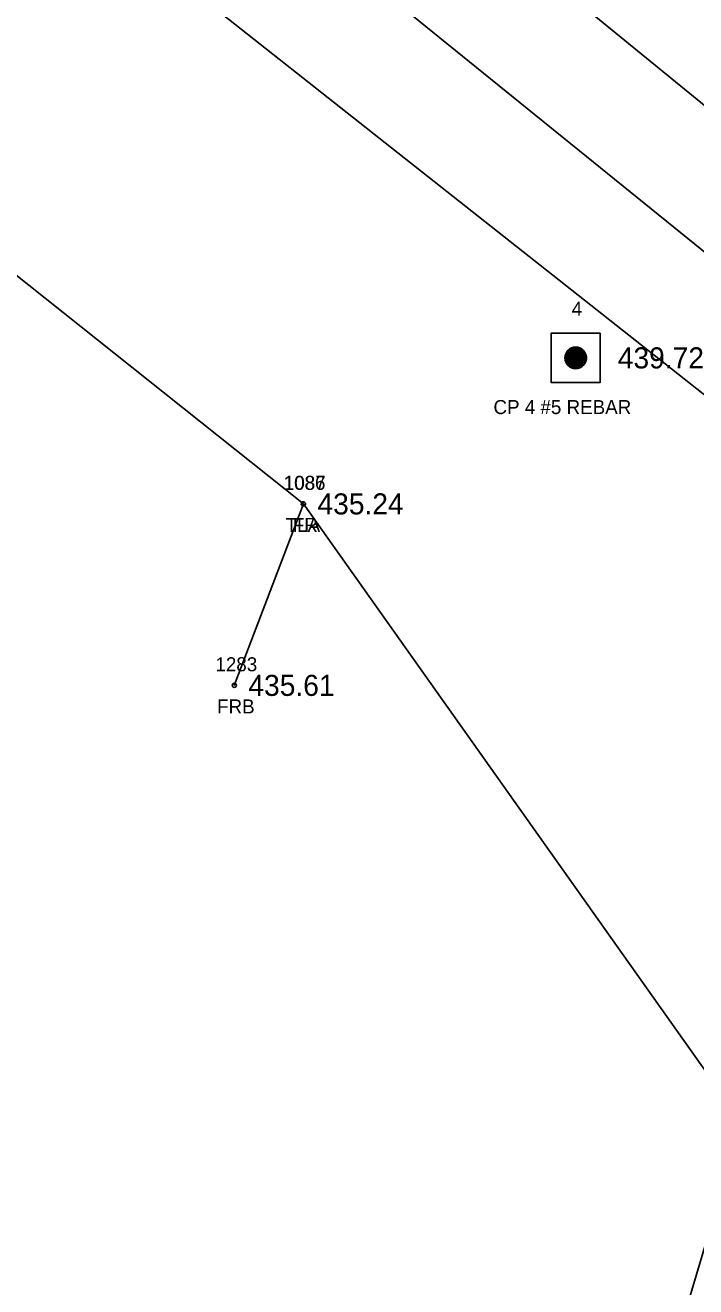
# Model space of a CAD drawing. Extents: x 1611865 to 1617004, y 775289 to 778546.
# Drawn here: x 1614381.3 to 1614429, y 777648.2 to 777738.1 of the extents above; entities that cross this region are included whole.
import ezdxf

# ---------------------------------------------------------------- set-up
doc = ezdxf.new("R2010")
doc.units = 0
for name, color, linetype in [('Default', 7, 'Continuous'), ('RD_EX_Fence_Other', 7, 'Continuous'), ('RD_EX_Fence_Other_txCode', 7, 'Continuous'), ('RD_EX_H2O', 7, 'Continuous'), ('RD_EX_Road', 7, 'Continuous'), ('RD_EX_TX_Fence_Other_ELEV', 7, 'Continuous'), ('RD_EX_TX_VEG_ELEV', 7, 'Continuous'), ('RD_EX_VEG', 7, 'Continuous'), ('RD_EX_VEG_txCode', 7, 'Continuous'), ('RD_HC_Cl', 7, 'Continuous'), ('RD_HC_Data', 7, 'Continuous'), ('RD_HC_Survey', 7, 'Continuous'), ('RD_HC_Survey_ELEV', 7, 'Continuous'), ('RD_HC_Survey_txCode', 7, 'Continuous'), ('RD_SMD_Locator', 7, 'Continuous')]:
    doc.layers.add(name, color=color, linetype=linetype)

msp = doc.modelspace()

# ---------------------------------------------------------------- linework, layer by layer
at = {"layer": 'Default'}
msp.add_line((1614235.771, 777878.843), (1615250.563, 777057.494), dxfattribs=at)
at = {"layer": 'RD_EX_Fence_Other'}
msp.add_lwpolyline([(1613852.079, 778066.008), (1613898.032, 778046.625), (1613942.243, 778026.725), (1613986.541, 778004.123), (1614028.517, 777979.951), (1614066.848, 777959.391), (1614112.817, 777929.404), (1614150.644, 777902.776), (1614189.706, 777873.346), (1614229.911, 777841.274), (1614268.423, 777810.693), (1614347.333, 777746.805), (1614401.116, 777703.978), (1614396.197, 777691.061)], dxfattribs=at)
at = {"layer": 'RD_EX_H2O'}
msp.add_lwpolyline([(1614634.128, 778230.422), (1614629.458, 778175.603), (1614612.201, 778126.551), (1614606.674, 778108.168), (1614610.575, 778089.24), (1614615.98, 778055.093), (1614603.68, 778033.92), (1614586.842, 777977.495), (1614567.105, 777927.459), (1614559.226, 777908.739), (1614527.556, 777868.787), (1614521.381, 777849.921), (1614507.997, 777820.034), (1614493.755, 777779.644), (1614479.272, 777749.866), (1614469.018, 777727.632), (1614464.372, 777721.672), (1614444.521, 777689.773), (1614435.763, 777671.493), (1614423.173, 777629.214)], dxfattribs=at)
at = {"layer": 'RD_EX_Road'}
for points in [[(1613868.873, 778104.152), (1613915.019, 778083.817), (1613960.162, 778062.2), (1614004.584, 778040.278), (1614048.838, 778015.985), (1614091.382, 777990.075), (1614134.355, 777962.6), (1614174.732, 777933.477), (1614192.07, 777920.583), (1614215.929, 777904.228), (1614254.595, 777873.045), (1614293.817, 777842.42), (1614371.745, 777779.588), (1614449.335, 777716.298), (1614443.983, 777709.717), (1614439.382, 777704.087)], [(1613862.136, 778087.922), (1613908.119, 778068.215), (1613952.955, 778047.38), (1613997.003, 778025.093), (1614041.162, 778001.628), (1614124.347, 777949.055), (1614164.513, 777920.905), (1614187.107, 777904.29), (1614205.267, 777889.822), (1614244.492, 777859.521), (1614283.421, 777829.445), (1614361.059, 777765.885), (1614439.382, 777704.087)]]:
    msp.add_lwpolyline(points, dxfattribs=at)
at = {"layer": 'RD_EX_VEG'}
msp.add_line((1614401.116, 777703.978), (1614430.331, 777662.765), dxfattribs=at)
at = {"layer": 'RD_HC_Cl'}
msp.add_line((1614235.771, 777878.843), (1615250.563, 777057.494), dxfattribs=at)
at = {"layer": 'RD_HC_Survey'}
for p, q in [((1614420.341, 777713.618), (1614420.341, 777715.125)), ((1614420.366, 777713.613), (1614420.366, 777715.13)), ((1614420.39, 777713.609), (1614420.39, 777715.134)), ((1614420.415, 777713.606), (1614420.415, 777715.137)), ((1614420.44, 777713.604), (1614420.44, 777715.139)), ((1614420.465, 777713.603), (1614420.465, 777715.14)), ((1614420.489, 777713.602), (1614420.489, 777715.141)), ((1614420.514, 777713.602), (1614420.514, 777715.141)), ((1614420.539, 777713.603), (1614420.539, 777715.14)), ((1614420.564, 777713.605), (1614420.564, 777715.138)), ((1614420.588, 777713.608), (1614420.588, 777715.135)), ((1614420.613, 777713.611), (1614420.613, 777715.132)), ((1614420.638, 777713.615), (1614420.638, 777715.128)), ((1614419.747, 777714.192), (1614419.747, 777714.55)), ((1614419.772, 777714.11), (1614419.772, 777714.633)), ((1614419.796, 777714.049), (1614419.796, 777714.693)), ((1614419.821, 777714), (1614419.821, 777714.742)), ((1614419.846, 777713.959), (1614419.846, 777714.784)), ((1614419.871, 777713.922), (1614419.871, 777714.821)), ((1614419.895, 777713.889), (1614419.895, 777714.853)), ((1614419.92, 777713.86), (1614419.92, 777714.883)), ((1614419.945, 777713.834), (1614419.945, 777714.909)), ((1614419.97, 777713.809), (1614419.97, 777714.933)), ((1614419.994, 777713.787), (1614419.994, 777714.956)), ((1614420.019, 777713.767), (1614420.019, 777714.976)), ((1614420.044, 777713.748), (1614420.044, 777714.995)), ((1614420.069, 777713.731), (1614420.069, 777715.012)), ((1614420.093, 777713.715), (1614420.093, 777715.028)), ((1614420.118, 777713.701), (1614420.118, 777715.042)), ((1614420.143, 777713.687), (1614420.143, 777715.055)), ((1614420.168, 777713.675), (1614420.168, 777715.068)), ((1614420.192, 777713.664), (1614420.192, 777715.079)), ((1614420.217, 777713.654), (1614420.217, 777715.089)), ((1614420.242, 777713.645), (1614420.242, 777715.098)), ((1614420.267, 777713.637), (1614420.267, 777715.106)), ((1614420.291, 777713.629), (1614420.291, 777715.113)), ((1614420.316, 777713.623), (1614420.316, 777715.12)), ((1614420.663, 777713.62), (1614420.663, 777715.122)), ((1614420.687, 777713.626), (1614420.687, 777715.117)), ((1614420.712, 777713.633), (1614420.712, 777715.11)), ((1614420.737, 777713.641), (1614420.737, 777715.102)), ((1614420.762, 777713.649), (1614420.762, 777715.093)), ((1614420.786, 777713.659), (1614420.786, 777715.084)), ((1614420.811, 777713.67), (1614420.811, 777715.073)), ((1614420.836, 777713.681), (1614420.836, 777715.061)), ((1614420.861, 777713.694), (1614420.861, 777715.049)), ((1614420.885, 777713.708), (1614420.885, 777715.035)), ((1614420.91, 777713.723), (1614420.91, 777715.019)), ((1614420.935, 777713.74), (1614420.935, 777715.003)), ((1614420.96, 777713.758), (1614420.96, 777714.985)), ((1614420.984, 777713.777), (1614420.984, 777714.965)), ((1614421.009, 777713.799), (1614421.009, 777714.944)), ((1614421.034, 777713.822), (1614421.034, 777714.921)), ((1614421.059, 777713.847), (1614421.059, 777714.896)), ((1614421.083, 777713.875), (1614421.083, 777714.868)), ((1614421.108, 777713.906), (1614421.108, 777714.837)), ((1614421.133, 777713.941), (1614421.133, 777714.802)), ((1614421.158, 777713.98), (1614421.158, 777714.763)), ((1614421.182, 777714.025), (1614421.182, 777714.718)), ((1614421.207, 777714.079), (1614421.207, 777714.664)), ((1614421.232, 777714.149), (1614421.232, 777714.594)), ((1614421.257, 777714.26), (1614421.257, 777714.483))]:
    msp.add_line(p, q, dxfattribs=at)
msp.add_lwpolyline([(1614422.245, 777716.121), (1614418.745, 777716.121), (1614418.745, 777712.621), (1614422.245, 777712.621)], close=True, dxfattribs=at)
msp.add_circle((1614420.495, 777714.371), 0.769, dxfattribs=at)
at = {"layer": 'RD_SMD_Locator'}
for centre in [(1614420.495, 777714.371), (1614401.116, 777703.978), (1614401.116, 777703.978), (1614396.197, 777691.061)]:
    msp.add_circle(centre, 0.15, dxfattribs=at)

# ---------------------------------------------------------------- texts
at = {"layer": 'RD_EX_Fence_Other_txCode'}
for s, p in [('1086', (1614399.706, 777704.978)), ('FR', (1614400.36, 777701.978)), ('1283', (1614394.851, 777692.061)), ('FRB', (1614394.969, 777689.061))]:
    msp.add_text(s, height=1, dxfattribs=at).set_placement(p)
at = {"layer": 'RD_EX_TX_Fence_Other_ELEV'}
for s, p in [('435.24', (1614402.116, 777703.228)), ('435.61', (1614397.197, 777690.311))]:
    msp.add_text(s, height=1.5, dxfattribs=at).set_placement(p)
at = {"layer": 'RD_EX_TX_VEG_ELEV'}
msp.add_text('435.24', height=1.5, dxfattribs=at).set_placement((1614402.116, 777703.228))
at = {"layer": 'RD_EX_VEG_txCode'}
for s, p in [('1087', (1614399.73, 777704.978)), ('TLA', (1614399.856, 777701.978))]:
    msp.add_text(s, height=1, dxfattribs=at).set_placement(p)
at = {"layer": 'RD_HC_Data'}
msp.add_text('S 21%%d 25\' 00" W', height=6, rotation=68.5833, dxfattribs=at).set_placement((1614427.571, 777621.924))
at = {"layer": 'RD_HC_Survey_ELEV'}
msp.add_text('439.72', height=1.5, dxfattribs=at).set_placement((1614423.495, 777713.621))
at = {"layer": 'RD_HC_Survey_txCode'}
for s, p in [('4', (1614420.212, 777717.371)), ('CP 4 #5 REBAR', (1614414.645, 777710.371))]:
    msp.add_text(s, height=1, dxfattribs=at).set_placement(p)

doc.saveas('drawing.dxf')
